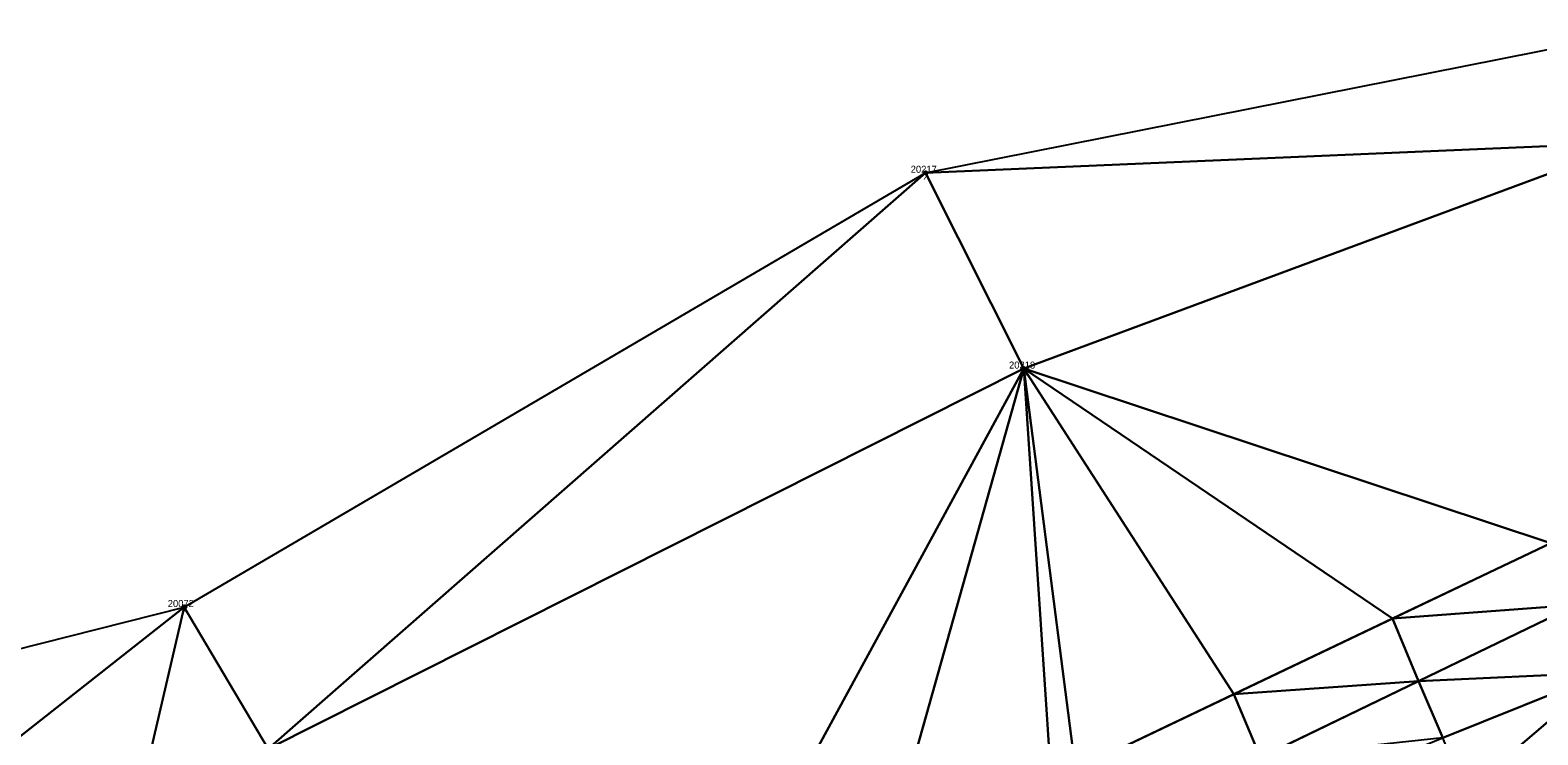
# Model space of a CAD drawing. Extents: x 1966740 to 1969291, y 1117379 to 1118460.
# Drawn here: x 1967411.8 to 1967626.6, y 1117798.6 to 1117899 of the extents above; entities that cross this region are included whole.
import ezdxf

# ---------------------------------------------------------------- set-up
doc = ezdxf.new("R2010")
doc.units = 0
for name, color, linetype in [('Level 3', 7, 'Continuous'), ('Level 30', 7, 'Continuous'), ('Level 35', 7, 'Continuous'), ('Level 52', 7, 'Continuous'), ('Level 62', 7, 'Continuous')]:
    doc.layers.add(name, color=color, linetype=linetype)

msp = doc.modelspace()

# ---------------------------------------------------------------- linework, layer by layer
at = {"layer": 'Level 3'}
for points in [[(1967560.73, 1117793.63), (1967650.63, 1117836.46), (1967680.95, 1117850.94), (1967690.95, 1117852.56), (1967700.5, 1117839.06)], [(1966768.15, 1117461.43), (1966869.41, 1117499.34), (1967070.52, 1117582.35), (1967171.25, 1117624.02), (1967269.74, 1117664.9), (1967320.21, 1117685.71), (1967369.37, 1117708.48), (1967468.51, 1117746.66), (1967564.6, 1117784.47), (1967654.68, 1117828.05), (1967680.1, 1117841.48), (1967687.91, 1117842.93), (1967691.45, 1117838.71), (1967693.03, 1117834.22)], [(1966769.51, 1117457.48), (1966870.16, 1117497.34), (1966971.19, 1117538.95), (1967071.09, 1117580.24), (1967172.6, 1117621.53), (1967270.79, 1117661.66), (1967321.12, 1117682.57), (1967371.52, 1117702.88), (1967470.26, 1117741.55), (1967566.67, 1117779.5), (1967661.25, 1117817.53), (1967694.4, 1117831.19), (1967697.89, 1117822.8)]]:
    msp.add_lwpolyline(points, dxfattribs=at)
at = {"layer": 'Level 30'}
for centre in [(1967539.35, 1117878.65), (1967553.36, 1117850.76), (1967433.7, 1117816.8)]:
    msp.add_circle(centre, 0.25, dxfattribs=at)
at = {"layer": 'Level 35'}
for points in [[(1967539.35, 1117878.65), (1967641.96, 1117898.96), (1967640.16, 1117882.97)], [(1967539.35, 1117878.65), (1967640.16, 1117882.97), (1967553.36, 1117850.76)], [(1967553.36, 1117850.76), (1967640.16, 1117882.97), (1967628.44, 1117825.89)], [(1967433.7, 1117816.8), (1967539.35, 1117878.65), (1967445.69, 1117796.58)], [(1967445.69, 1117796.58), (1967539.35, 1117878.65), (1967553.36, 1117850.76)], [(1967445.69, 1117796.58), (1967553.36, 1117850.76), (1967511.09, 1117773.03)], [(1967511.09, 1117773.03), (1967553.36, 1117850.76), (1967534.17, 1117782.61)], [(1967534.17, 1117782.61), (1967553.36, 1117850.76), (1967557.25, 1117792.19)], [(1967553.36, 1117850.76), (1967628.44, 1117825.89), (1967605.87, 1117815.14)], [(1967553.36, 1117850.76), (1967605.87, 1117815.14), (1967583.3, 1117804.39)], [(1967553.36, 1117850.76), (1967583.3, 1117804.39), (1967560.73, 1117793.63)], [(1967553.36, 1117850.76), (1967560.73, 1117793.63), (1967557.25, 1117792.19)], [(1967605.87, 1117815.14), (1967628.44, 1117825.89), (1967632.11, 1117817.13)], [(1967343.9, 1117794.1), (1967433.7, 1117816.8), (1967352.83, 1117753.13)], [(1967352.83, 1117753.13), (1967433.7, 1117816.8), (1967414.52, 1117734.37)], [(1967414.52, 1117734.37), (1967433.7, 1117816.8), (1967445.69, 1117796.58)], [(1967605.87, 1117815.14), (1967632.11, 1117817.13), (1967609.61, 1117806.25)], [(1967609.61, 1117806.25), (1967632.11, 1117817.13), (1967636.26, 1117807.48)], [(1967583.3, 1117804.39), (1967605.87, 1117815.14), (1967609.61, 1117806.25)], [(1967609.61, 1117806.25), (1967636.26, 1117807.48), (1967613.06, 1117798.15)], [(1967613.06, 1117798.15), (1967636.26, 1117807.48), (1967616.27, 1117790.36)], [(1967616.27, 1117790.36), (1967636.26, 1117807.48), (1967639.5, 1117799.59)], [(1967583.3, 1117804.39), (1967609.61, 1117806.25), (1967587.1, 1117795.36)], [(1967587.1, 1117795.36), (1967609.61, 1117806.25), (1967613.06, 1117798.15)], [(1967560.73, 1117793.63), (1967583.3, 1117804.39), (1967587.1, 1117795.36)]]:
    msp.add_lwpolyline(points, close=True, dxfattribs=at)

# ---------------------------------------------------------------- texts
at = {"layer": 'Level 52'}
for s, p in [('20217', (1967537.24, 1117878.65)), ('20218', (1967551.25, 1117850.76)), ('20072', (1967431.37, 1117816.8))]:
    msp.add_text(s, height=1, dxfattribs=at).set_placement(p)
at = {"layer": 'Level 62'}
for p in [(1967539.02, 1117877.65), (1967553.02, 1117849.76), (1967433.37, 1117815.8)]:
    msp.add_text('X', height=1, dxfattribs=at).set_placement(p)

doc.saveas('drawing.dxf')
